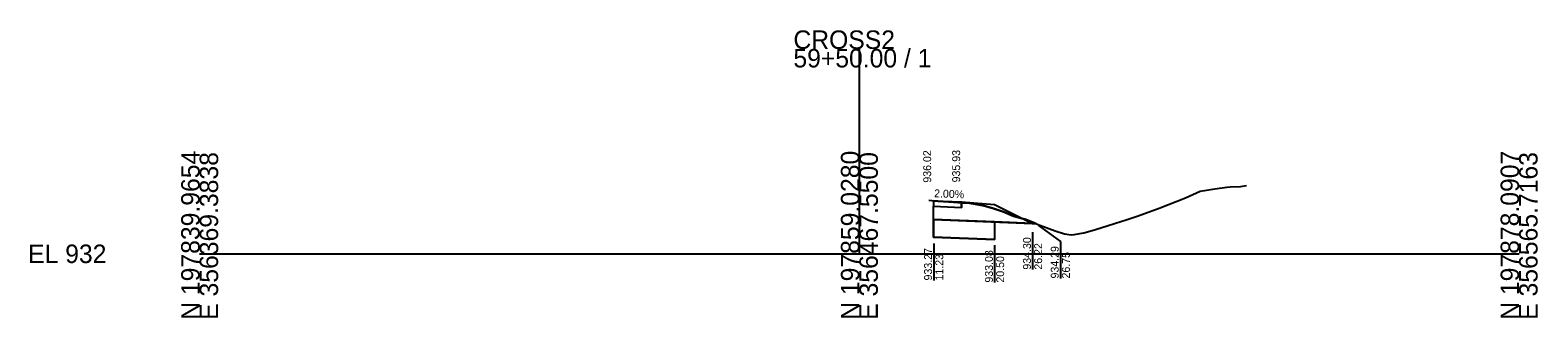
# Model space of a CAD drawing. Extents: x -26 to 203, y -10 to 14021.
# Drawn here: x -25.7 to 202.8, y 490.3 to 533.9 of the extents above; entities that cross this region are included whole.
import ezdxf

# ---------------------------------------------------------------- set-up
doc = ezdxf.new("R2010")
doc.units = 0
for name, color, linetype in [('Default', 7, 'Continuous'), ('P_E_XS_Ground', 7, 'Continuous'), ('P_XS', 7, 'Continuous'), ('P_XS_EAR_CommonGrnd', 7, 'Continuous'), ('P_XS_Lane', 7, 'Continuous'), ('P_XS_Rock', 7, 'Continuous')]:
    doc.layers.add(name, color=color, linetype=linetype)

msp = doc.modelspace()

# ---------------------------------------------------------------- linework, layer by layer
at = {"layer": 'Default'}
for p, q in [((100, 500), (100, 531.02)), ((0, 500), (100, 500)), ((100, 500), (200, 500))]:
    msp.add_line(p, q, dxfattribs=at)
at = {"layer": 'P_E_XS_Ground'}
for p, q in [((151.64, 509.49), (153.89, 509.82)), ((153.89, 509.82), (155.69, 510.09)), ((155.69, 510.09), (156.21, 510.16)), ((156.21, 510.16), (157.75, 510.18)), ((157.75, 510.18), (158.69, 510.34)), ((110.52, 508.11), (111.9, 507.97)), ((111.9, 507.97), (113.55, 507.86)), ((113.55, 507.86), (114.94, 507.76)), ((114.94, 507.76), (116.4, 507.71)), ((116.4, 507.71), (117.27, 507.57)), ((117.27, 507.57), (118.92, 507.24)), ((145.46, 506.89), (149.42, 508.49)), ((149.42, 508.49), (151.64, 509.49)), ((118.92, 507.24), (120.16, 506.91)), ((120.16, 506.91), (121.87, 506.34)), ((121.87, 506.34), (123.34, 505.68)), ((123.34, 505.68), (125.1, 505.23)), ((125.1, 505.23), (127.37, 504.34)), ((137.71, 504.3), (140.57, 505.21)), ((140.57, 505.21), (142.27, 505.73)), ((142.27, 505.73), (145.46, 506.89)), ((127.37, 504.34), (129.66, 503.47)), ((129.66, 503.47), (131.08, 503.04)), ((131.08, 503.04), (132.1, 502.85)), ((132.1, 502.85), (132.56, 502.94)), ((132.56, 502.94), (134.02, 503.18)), ((134.02, 503.18), (135.62, 503.62)), ((135.62, 503.62), (137.71, 504.3))]:
    msp.add_line(p, q, dxfattribs=at)
at = {"layer": 'P_XS'}
for p, q in [((111.23, 508.04), (111.23, 507.2)), ((115.5, 507.87), (115.5, 507.03)), ((111.23, 507.2), (115.5, 507.03)), ((111.23, 505.2), (111.23, 507.2)), ((111.23, 505.2), (126.22, 504.61)), ((111.23, 505.2), (111.23, 502.54)), ((120.5, 504.83), (120.5, 502.17)), ((111.23, 502.54), (120.5, 502.17))]:
    msp.add_line(p, q, dxfattribs=at)
at = {"layer": 'P_XS_EAR_CommonGrnd'}
for points in [[(111.23, 507.2), (115.5, 507.03), (115.5, 507.74), (114.94, 507.76), (113.55, 507.86), (111.9, 507.97), (111.23, 508.04)], [(111.23, 508.04), (115.5, 507.87), (115.5, 507.74), (114.94, 507.76), (113.55, 507.86), (111.9, 507.97)], [(117.27, 507.57), (118.92, 507.24), (120.16, 506.91), (121.87, 506.34), (123.34, 505.68), (124.83, 505.3), (126.22, 504.61), (120.5, 504.83), (111.23, 505.2), (111.23, 507.2), (115.5, 507.03), (115.5, 507.74), (116.4, 507.71)], [(115.5, 507.87), (120.5, 507.47), (124.83, 505.3), (123.34, 505.68), (121.87, 506.34), (120.16, 506.91), (118.92, 507.24), (117.27, 507.57), (116.4, 507.71), (115.5, 507.74)], [(120.5, 504.83), (120.5, 502.17), (111.23, 502.54), (111.23, 505.2)], [(126.22, 504.61), (126.75, 504.58), (125.1, 505.23), (124.83, 505.3)]]:
    msp.add_lwpolyline(points, close=True, dxfattribs=at)
at = {"layer": 'P_XS_Lane'}
for p, q in [((111.23, 508.04), (115.5, 507.87)), ((115.5, 507.87), (120.5, 507.47)), ((120.5, 507.47), (126.22, 504.61)), ((126.22, 504.61), (126.75, 504.58))]:
    msp.add_line(p, q, dxfattribs=at)
at = {"layer": 'P_XS_Rock'}
for p, q in [((126.25, 503.3), (126.25, 497.6)), ((127.17, 504.27), (130.46, 501.86)), ((111.26, 501.56), (111.26, 495.96)), ((120.49, 501.33), (120.49, 495.64)), ((130.46, 501.86), (130.46, 496.26))]:
    msp.add_line(p, q, dxfattribs=at)

# ---------------------------------------------------------------- texts
at = {"layer": 'Default'}
for s, p in [('CROSS2', (90, 531.02)), ('59+50.00 / 1', (90, 528.22)), ('EL 932', (-26, 498.6))]:
    msp.add_text(s, height=2.8, dxfattribs=at).set_placement(p)
for s, p in [('N 197839.9654', (0, 490)), ('E 356369.3838', (2.8, 490)), ('N 197859.0280', (100, 490)), ('E 356467.5500', (102.8, 490)), ('N 197878.0907', (200, 490)), ('E 356565.7163', (202.8, 490))]:
    msp.add_text(s, height=2.8, rotation=90, dxfattribs=at).set_placement(p)
at = {"layer": 'P_XS_Rock'}
for s, rotation, p in [('936.02', 90, (110.88, 510.77)), ('935.93', 90, (115.27, 510.81)), ('2.00%', 357.7094, (111.31, 508.57)), ('933.27', 90, (111.01, 495.96)), ('934.30', 90, (126, 497.6)), ('26.22', 90, (127.7, 497.6)), ('934.29', 90, (130.21, 496.26)), ('11.23', 90, (112.71, 495.96)), ('933.08', 90, (120.24, 495.64)), ('20.50', 90, (121.94, 495.64)), ('26.75', 90, (131.91, 496.26))]:
    msp.add_text(s, height=1.2, rotation=rotation, dxfattribs=at).set_placement(p)

doc.saveas('drawing.dxf')
